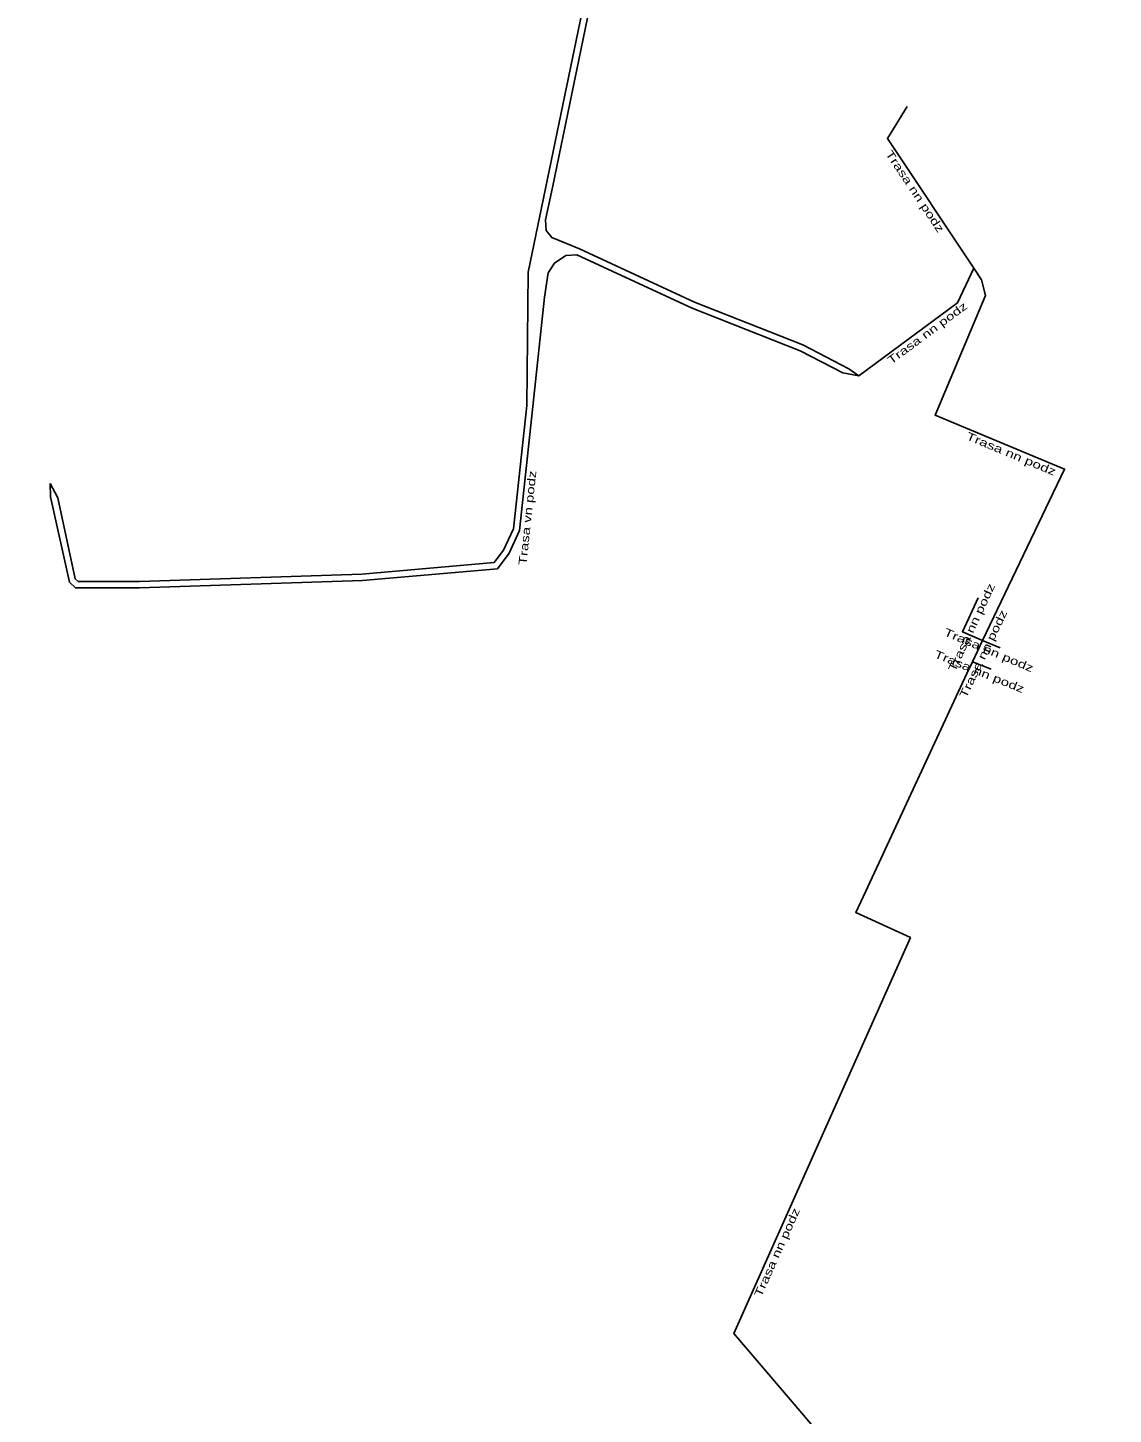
# Model space of a CAD drawing. Extents: x -733620 to -732615, y -1025255 to -1024617.
# Drawn here: x -733116.1 to -733048.3, y -1025041.4 to -1024954.7 of the extents above; entities that cross this region are included whole.
import ezdxf
from ezdxf.enums import TextEntityAlignment as Align

# ---------------------------------------------------------------- set-up
doc = ezdxf.new("R2010")
doc.units = 0
doc.header["$LTSCALE"] = 0.2
doc.linetypes.add('MEDIUM_DASHED', pattern=[4.5, 3, -1.5])
doc.layers.add('11', color=7, linetype='MEDIUM_DASHED', lineweight=25)
doc.layers.add('21', color=7, linetype='Continuous', lineweight=25)
doc.layers.add('20', color=7, linetype='Continuous')

msp = doc.modelspace()

# ---------------------------------------------------------------- linework, layer by layer
at = {"layer": '11', "linetype": 'Continuous'}
for p, q in [((-733056.44, -1024993.02), (-733057.075, -1024994.348)), ((-733055.35, -1024993.48), (-733056.44, -1024993.02))]:
    msp.add_line(p, q, dxfattribs=at)
for points in [[(-733061.16, -1024959.66), (-733062.38, -1024961.67), (-733056.99, -1024969.77)], [(-733056.99, -1024969.77), (-733058.01, -1024971.92), (-733064.167, -1024976.484)], [(-733056.99, -1024969.77), (-733056.5, -1024970.5), (-733056.26, -1024971.47), (-733059.41, -1024978.95), (-733051.32, -1024982.31), (-733056.44, -1024993.02)], [(-733056.44, -1024993.02), (-733057.695, -1024992.474), (-733056.707, -1024990.349)], [(-733057.075, -1024994.348), (-733057.43, -1024995.09), (-733063.74, -1025008.67), (-733064.36, -1025010), (-733060.95, -1025011.58), (-733071.97, -1025036.3), (-733067.72, -1025041.29), (-733050.88, -1025061.18), (-733048.28, -1025064.26)], [(-733055.91, -1024994.82), (-733057.07, -1024994.35), (-733057.075, -1024994.348)]]:
    msp.add_lwpolyline(points, dxfattribs=at)
at = {"layer": '21'}
for points in [[(-733064.167, -1024976.484), (-733064.8, -1024976.055), (-733067.669, -1024974.555), (-733074.425, -1024971.891), (-733081.614, -1024968.561), (-733083.346, -1024967.839), (-733083.705, -1024967.4), (-733083.732, -1024966.753), (-733083.299, -1024964.717), (-733079.617, -1024946.843), (-733080.539, -1024938.355), (-733076.37, -1024924.754), (-733069.811, -1024911.621), (-733069.674, -1024911.019), (-733069.929, -1024909.134), (-733070.34, -1024907.685), (-733070.671, -1024907.144), (-733079.339, -1024904.001), (-733096.073, -1024897.023), (-733123.483, -1024882.599)], [(-733123.677, -1024882.949), (-733096.243, -1024897.385), (-733079.479, -1024904.377), (-733071.002, -1024907.369), (-733070.737, -1024907.783), (-733070.324, -1024909.114), (-733070.084, -1024910.916), (-733070.205, -1024911.541), (-733076.757, -1024924.596), (-733080.92, -1024938.342), (-733080.014, -1024946.778), (-733084.821, -1024970.004), (-733084.893, -1024978.341), (-733085.743, -1024986.047), (-733086.354, -1024987.367), (-733086.948, -1024988.155), (-733095.2, -1024988.87), (-733109.097, -1024989.335), (-733112.927, -1024989.335), (-733113.099, -1024989.174), (-733114.199, -1024984.103), (-733114.673, -1024983.212)], [(-733064.167, -1024976.484), (-733065.176, -1024976.306), (-733067.835, -1024974.919), (-733074.583, -1024972.259), (-733081.782, -1024968.923), (-733082.475, -1024968.979), (-733083.178, -1024969.444), (-733083.578, -1024970.051), (-733083.806, -1024971.564), (-733084.523, -1024978.402), (-733085.353, -1024986.155), (-733086.008, -1024987.573), (-733086.736, -1024988.539), (-733095.174, -1024989.27), (-733109.093, -1024989.735), (-733113.085, -1024989.735), (-733113.463, -1024989.38), (-733114.65, -1024984.049), (-733114.673, -1024983.212)]]:
    msp.add_lwpolyline(points, dxfattribs=at)

# ---------------------------------------------------------------- texts
at = {"layer": '20', "width": 1.4}
for s, rotation, p in [('Trasa nn podz', 303.641, (-733060.8766, -1024965.101)), ('Trasa nn podz', 36.544, (-733059.7454, -1024974.0151)), ('Trasa nn podz', 337.446, (-733054.7474, -1024981.5895)), ('Trasa vn podz', 83.889, (-733084.6164, -1024985.3781)), ('Trasa nn podz', 65.072, (-733056.8999, -1024992.3049)), ('Trasa nn podz', 64.449, (-733056.1713, -1024993.9633)), ('Trasa nn podz', 337.119, (-733056.1477, -1024993.8493)), ('Trasa nn podz', 337.944, (-733056.7364, -1024995.1865)), ('Trasa nn podz', 65.973, (-733069.0463, -1025031.3393))]:
    msp.add_text(s, height=0.5, rotation=rotation, dxfattribs=at).set_placement(p, align=Align.CENTER)

doc.saveas('drawing.dxf')
